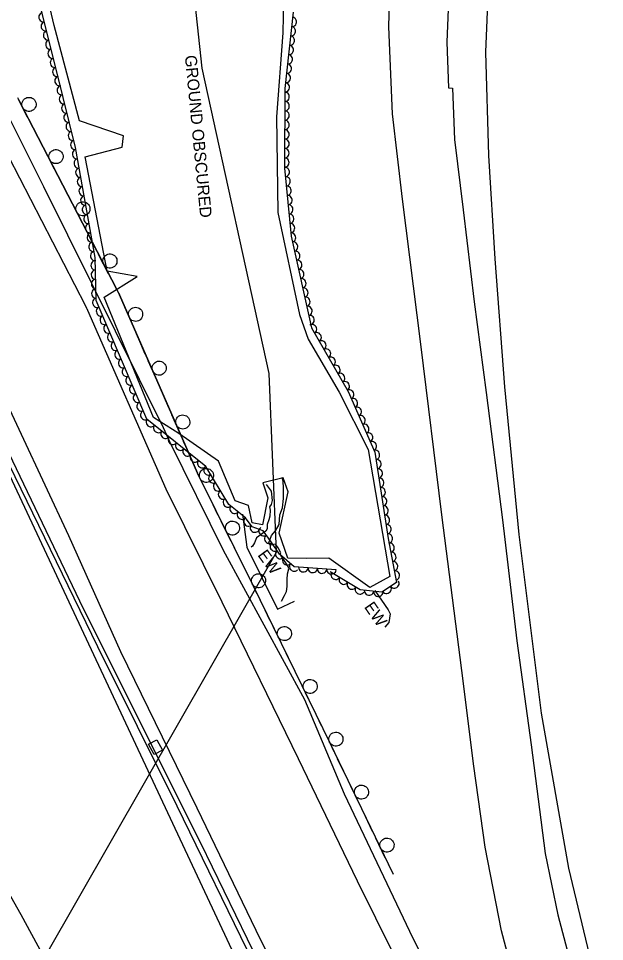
# Model space of a CAD drawing. Extents: x 1746719 to 1766531, y 631721 to 662391.
# Drawn here: x 1761949.9 to 1762199.1, y 638199.1 to 638591.9 of the extents above; entities that cross this region are included whole.
import ezdxf

# ---------------------------------------------------------------- set-up
doc = ezdxf.new("R2010")
doc.units = 0
for name, color, linetype in [('SURVEY - AERIAL SURVEY - Photo Control - Points - Elevations', 7, 'Continuous'), ('SURVEY - AERIAL SURVEY - Photo Control - Points - Locators', 7, 'Continuous'), ('SURVEY - AERIAL SURVEY - Photo Control - Points - Numbers', 7, 'Continuous'), ('SURVEY - AERIAL SURVEY - Photo Control with Text', 7, 'Continuous'), ('SURVEY - CENTERLINE - Existing Roads Text', 7, 'Continuous'), ('SURVEY - CENTERLINE - Preliminary - Development', 7, 'Continuous'), ('SURVEY - CENTERLINE - Preliminary Curve Text', 7, 'Continuous'), ('SURVEY - CONTROL - Points - Locators', 7, 'Continuous')]:
    doc.layers.add(name, color=color, linetype=linetype)

msp = doc.modelspace()

# ---------------------------------------------------------------- linework, layer by layer
at = {"layer": 'SURVEY - AERIAL SURVEY - Photo Control - Points - Elevations'}
for p, q in [((1761949.91, 638557.44), (1761991.7, 638476.49)), ((1761936.58, 638550.56), (1761978.37, 638469.61)), ((1761991.7, 638476.49), (1761992.26, 638475.36)), ((1761992.26, 638475.36), (1761992.44, 638475.01)), ((1761992.44, 638475.01), (1761992.81, 638474.22)), ((1761992.81, 638474.22), (1762026.02, 638398.33)), ((1761978.37, 638469.61), (1761978.85, 638468.64)), ((1761978.85, 638468.64), (1761978.96, 638468.43)), ((1761978.96, 638468.43), (1761979.28, 638467.75)), ((1761979.28, 638467.75), (1762012.58, 638391.68)), ((1761935.82, 638447.38), (1761971.22, 638371.82))]:
    msp.add_line(p, q, dxfattribs=at)
for points in [[(1762189.51, 638754.92), (1762177.71, 638725.71), (1762163.21, 638683.11), (1762156.01, 638652.95), (1762150.08, 638615.49), (1762148.44, 638577.48), (1762149.79, 638533.52), (1762152.38, 638489.61), (1762156.49, 638435.15), (1762162.6, 638372.26), (1762172.14, 638296.33), (1762183.74, 638230.35), (1762199.06, 638166.32)], [(1762133.07, 638606.45), (1762131.97, 638581.73), (1762132.71, 638562.3), (1762134.49, 638562.24), (1762135.23, 638540.36), (1762138.97, 638510.45), (1762143.59, 638471.26), (1762148.75, 638432.72), (1762155.64, 638378.5), (1762161.73, 638327.1), (1762167.84, 638282.76), (1762173.86, 638236.63), (1762179.27, 638210.46), (1762192.08, 638161.63)], [(1762161.96, 638178.55), (1762155.3, 638203.64), (1762148.37, 638239.24), (1762143.48, 638273.66), (1762138.44, 638314.43), (1762129.83, 638380.73), (1762120.98, 638453.32), (1762113.14, 638514.96), (1762108.92, 638551.33), (1762107.4, 638588.32), (1762107.75, 638604.5)], [(1762142.79, 638124.38), (1762142.25, 638125.93), (1762150.96, 638131.28), (1762152.3, 638133.24), (1762153.55, 638134.98), (1762150.91, 638140.96), (1762149.05, 638144.96), (1762147.4, 638144.71), (1762146.19, 638145.03), (1762139.53, 638157.74), (1762117.72, 638200.33), (1762088.54, 638261.83), (1762071.72, 638301.89), (1762037.11, 638365.51), (1762014.19, 638411.73), (1762011.63, 638417.62), (1761960.63, 638520.21), (1761945.31, 638551.2)], [(1761420.3, 638505.12), (1761469.25, 638488.5), (1761533.06, 638468.42), (1761595.06, 638448.42), (1761650.97, 638430.46), (1761705.66, 638412.37), (1761764.6, 638389.95), (1761796.37, 638373.31), (1761821.32, 638357.68), (1761844.39, 638340.34), (1761865.8, 638322.04), (1761884.68, 638304.7), (1761900.43, 638287.9), (1761915.32, 638268.65), (1761930.12, 638247.32), (1761950.94, 638210.57), (1761971.76, 638172.11)], [(1761924.95, 638442.29), (1762056.31, 638161.91), (1762090.32, 638088.89)], [(1762012.58, 638391.68), (1762036.31, 638343.69), (1762068.88, 638276.96), (1762093.91, 638224.95), (1762124.89, 638162.28), (1762146.1, 638118.84)], [(1761971.22, 638371.82), (1761993.23, 638322.52), (1762025.68, 638256.03), (1762050.77, 638203.91), (1762081.81, 638141.12), (1762102.97, 638097.78)]]:
    msp.add_lwpolyline(points, dxfattribs=at)
at = {"layer": 'SURVEY - AERIAL SURVEY - Photo Control - Points - Locators'}
msp.add_lwpolyline([(1762062.99, 638621.31), (1762062.3, 638585.77), (1762059.63, 638550), (1762060.15, 638509.36), (1762069.42, 638465.91), (1762073.07, 638455.39), (1762086.27, 638432.83), (1762098.56, 638408.51), (1762107.82, 638354.38), (1762099.24, 638349.68), (1762081.8, 638362.27), (1762072.39, 638362.09), (1762064.43, 638362.22), (1762060.78, 638372.82), (1762064.59, 638390.45), (1762062.38, 638396.34), (1762053.78, 638394.27), (1762055.86, 638387.85), (1762053.64, 638376.42), (1762049.24, 638377.28), (1762047.65, 638384.6), (1762042.08, 638386.6), (1762034.92, 638403.44), (1762018.1, 638415.27), (1762007.28, 638422.08), (1761986.37, 638473.28), (1762000.43, 638482.07), (1761987.63, 638484.37), (1761978.2, 638532.96), (1761994.05, 638537.11), (1761994.6, 638541.94), (1761975.88, 638548.34), (1761965.03, 638588.81), (1761955.97, 638627.59)], dxfattribs=at)
at = {"layer": 'SURVEY - AERIAL SURVEY - Photo Control - Points - Numbers'}
for p, q in [((1761991.7, 638476.49), (1761949.91, 638557.44)), ((1762026.02, 638398.33), (1761992.81, 638474.22)), ((1761929.92, 638439.81), (1761975.88, 638344.11)), ((1761983.71, 638324.44), (1761938.79, 638416.64)), ((1761975.88, 638344.11), (1761987.01, 638321.54)), ((1762017.38, 638256.74), (1761983.71, 638324.44)), ((1761987.01, 638321.54), (1762027.33, 638241.16)), ((1762062.98, 638162.91), (1762017.38, 638256.74)), ((1762027.33, 638241.16), (1762066.4, 638160.85))]:
    msp.add_line(p, q, dxfattribs=at)
for points in [[(1761953.81, 638549.88), (1761949.91, 638557.44), (1761949.91, 638557.45), (1761949.59, 638558.06)], [(1761957.43, 638542.86), (1761955.28, 638547.04)], [(1761959.59, 638538.69), (1761957.43, 638542.86)], [(1761965.28, 638527.67), (1761961.06, 638535.84)], [(1761968.9, 638520.65), (1761966.74, 638524.83)], [(1761971.06, 638516.47), (1761968.9, 638520.65)], [(1761976.74, 638505.45), (1761972.52, 638513.63)], [(1761980.37, 638498.44), (1761978.21, 638502.61)], [(1761982.52, 638494.26), (1761980.37, 638498.44)], [(1761988.21, 638483.24), (1761983.99, 638491.42)], [(1761991.83, 638476.22), (1761991.7, 638476.49), (1761989.68, 638480.4)], [(1761993.8, 638471.95), (1761992.81, 638474.22), (1761991.83, 638476.22)], [(1761998.78, 638460.59), (1761995.09, 638469.02)], [(1762001.94, 638453.36), (1762000.06, 638457.66)], [(1762003.83, 638449.05), (1762001.94, 638453.36)], [(1762008.8, 638437.69), (1762005.11, 638446.12)], [(1762011.97, 638430.45), (1762010.08, 638434.76)], [(1762013.85, 638426.15), (1762011.97, 638430.45)], [(1762018.82, 638414.79), (1762015.13, 638423.22)], [(1762021.99, 638407.55), (1762020.1, 638411.86)], [(1762023.87, 638403.24), (1762021.99, 638407.55)], [(1762029.14, 638392.02), (1762026.02, 638398.33), (1762026.02, 638398.33), (1762025.15, 638400.31)], [(1762109.28, 638227.61), (1762082.38, 638283.5), (1762049.78, 638350.31), (1762026.02, 638398.33)], [(1762032.64, 638384.94), (1762030.56, 638389.16)], [(1762034.73, 638380.73), (1762032.64, 638384.94)], [(1762040.23, 638369.61), (1762036.15, 638377.86)], [(1762043.73, 638362.53), (1762041.64, 638366.75)], [(1762045.81, 638358.32), (1762043.73, 638362.53)], [(1762051.29, 638347.2), (1762049.78, 638350.31), (1762047.23, 638355.45)], [(1762054.76, 638340.1), (1762052.7, 638344.32)], [(1762056.82, 638335.88), (1762054.76, 638340.1)], [(1762062.26, 638324.73), (1762058.22, 638333)], [(1762065.72, 638317.63), (1762063.66, 638321.85)], [(1762067.78, 638313.41), (1762065.72, 638317.63)], [(1762073.22, 638302.26), (1762069.19, 638310.53)], [(1762076.69, 638295.16), (1762074.62, 638299.39)], [(1762078.75, 638290.94), (1762076.69, 638295.16)], [(1762084.17, 638279.79), (1762082.38, 638283.5), (1762080.15, 638288.06)], [(1762087.59, 638272.67), (1762085.55, 638276.9)], [(1762089.63, 638268.43), (1762087.59, 638272.67)], [(1762095.01, 638257.26), (1762091.02, 638265.55)], [(1762098.43, 638250.14), (1762096.4, 638254.38)], [(1762100.47, 638245.91), (1762098.43, 638250.14)], [(1762105.85, 638234.73), (1762101.86, 638243.02)], [(1762109.28, 638227.61), (1762107.24, 638231.85)]]:
    msp.add_lwpolyline(points, dxfattribs=at)
for centre, start, end in [((1761954.38, 638555.31), 320.571, 320.557), ((1761965.85, 638533.09), 320.571, 320.557), ((1761977.32, 638510.88), 320.571, 320.557), ((1761988.79, 638488.66), 320.571, 320.557), ((1761999.7, 638465.97), 316.9016, 316.8876), ((1762009.72, 638443.07), 316.9016, 316.8876), ((1762019.74, 638420.16), 316.9016, 316.8876), ((1762029.81, 638397.44), 319.5889, 319.5749), ((1762040.89, 638375.03), 319.5889, 319.5749), ((1762051.98, 638352.62), 319.5889, 319.5749), ((1762062.95, 638330.14), 319.2802, 319.2662), ((1762073.92, 638307.67), 319.2802, 319.2662), ((1762084.88, 638285.21), 319.2802, 319.2662), ((1762095.73, 638262.67), 318.9714, 318.9574), ((1762106.58, 638240.14), 318.9714, 318.9574)]:
    msp.add_arc(centre, 3, start, end, dxfattribs=at)
at = {"layer": 'SURVEY - AERIAL SURVEY - Photo Control with Text'}
for points in [[(1762084.98, 638357.21), (1762067.17, 638358.5), (1762060.95, 638363.99), (1762057.35, 638369.19), (1762053.95, 638373.8), (1762049.31, 638375.52), (1762046.38, 638379.44), (1762039.31, 638385.06), (1762029.59, 638401.22), (1762004.42, 638421.41), (1761982.95, 638471.79), (1761982.53, 638490.14), (1761974.2, 638536.92), (1761966.41, 638568.62), (1761951.57, 638627.58)], [(1762066.69, 638594.6), (1762063.19, 638562.1), (1762063.07, 638528.17), (1762065.79, 638499.26), (1762074.49, 638460.19), (1762090.07, 638433.11), (1762101.4, 638407.29), (1762107.06, 638370.54), (1762110.58, 638351.87), (1762104.32, 638347.69), (1762095.15, 638348.74), (1762082.48, 638356.44)]]:
    msp.add_lwpolyline(points, dxfattribs=at)
for centre, major_axis in [((1761960.43, 638592.4), (-0.49, 1.94)), ((1761961.4, 638588.52), (-0.49, 1.94)), ((1762066.24, 638590.38), (-0.21, -1.99)), ((1761962.38, 638584.64), (-0.49, 1.94)), ((1762065.81, 638586.4), (-0.21, -1.99)), ((1761963.36, 638580.76), (-0.49, 1.94)), ((1762065.38, 638582.42), (-0.21, -1.99)), ((1761964.33, 638576.88), (-0.49, 1.94)), ((1762064.95, 638578.44), (-0.21, -1.99)), ((1761965.31, 638573), (-0.49, 1.94)), ((1762064.53, 638574.47), (-0.21, -1.99)), ((1761966.29, 638569.12), (-0.49, 1.94)), ((1762064.1, 638570.49), (-0.21, -1.99)), ((1761967.25, 638565.24), (-0.48, 1.94)), ((1762063.67, 638566.51), (-0.21, -1.99)), ((1761968.2, 638561.35), (-0.48, 1.94)), ((1762063.24, 638562.54), (-0.21, -1.99)), ((1761969.15, 638557.47), (-0.48, 1.94)), ((1762063.18, 638558.54), (-0.01, -2)), ((1761970.11, 638553.59), (-0.48, 1.94)), ((1762063.17, 638554.54), (-0.01, -2)), ((1761971.06, 638549.7), (-0.48, 1.94)), ((1762063.15, 638550.54), (-0.01, -2)), ((1761972.02, 638545.82), (-0.48, 1.94)), ((1762063.14, 638546.54), (-0.01, -2)), ((1761972.97, 638541.93), (-0.48, 1.94)), ((1762063.12, 638542.54), (-0.01, -2)), ((1761973.93, 638538.05), (-0.48, 1.94)), ((1762063.11, 638538.54), (-0.01, -2)), ((1761974.7, 638534.12), (-0.35, 1.97)), ((1762063.09, 638534.54), (-0.01, -2)), ((1761975.4, 638530.19), (-0.35, 1.97)), ((1762063.07, 638530.54), (-0.01, -2)), ((1761976.1, 638526.25), (-0.35, 1.97)), ((1762063.22, 638526.55), (0.19, -1.99)), ((1761976.8, 638522.31), (-0.35, 1.97)), ((1762063.59, 638522.56), (0.19, -1.99)), ((1761977.5, 638518.37), (-0.35, 1.97)), ((1762063.97, 638518.58), (0.19, -1.99)), ((1761978.2, 638514.43), (-0.35, 1.97)), ((1762064.35, 638514.6), (0.19, -1.99)), ((1761978.9, 638510.5), (-0.35, 1.97)), ((1762064.72, 638510.62), (0.19, -1.99)), ((1761979.6, 638506.56), (-0.35, 1.97)), ((1762065.1, 638506.63), (0.19, -1.99)), ((1761980.3, 638502.62), (-0.35, 1.97)), ((1762065.47, 638502.65), (0.19, -1.99)), ((1761981.01, 638498.68), (-0.35, 1.97)), ((1762065.92, 638498.68), (0.43, -1.95)), ((1761981.71, 638494.74), (-0.35, 1.97)), ((1762066.79, 638494.78), (0.43, -1.95)), ((1761982.41, 638490.8), (-0.35, 1.97)), ((1762067.66, 638490.87), (0.43, -1.95)), ((1761982.6, 638486.82), (-0.05, 2)), ((1762068.53, 638486.97), (0.43, -1.95)), ((1761982.69, 638482.82), (-0.05, 2)), ((1762069.4, 638483.06), (0.43, -1.95)), ((1761982.78, 638478.82), (-0.05, 2)), ((1762070.27, 638479.16), (0.43, -1.95)), ((1761982.88, 638474.82), (-0.05, 2)), ((1762071.14, 638475.25), (0.43, -1.95)), ((1761983.32, 638470.9), (-0.78, 1.84)), ((1762072.01, 638471.35), (0.43, -1.95)), ((1761984.89, 638467.22), (-0.78, 1.84)), ((1762072.88, 638467.45), (0.43, -1.95)), ((1761986.46, 638463.54), (-0.78, 1.84)), ((1762073.75, 638463.54), (0.43, -1.95)), ((1761988.03, 638459.86), (-0.78, 1.84)), ((1762074.78, 638459.7), (1, -1.73)), ((1761989.6, 638456.18), (-0.78, 1.84)), ((1762076.77, 638456.23), (1, -1.73)), ((1761991.17, 638452.5), (-0.78, 1.84)), ((1762078.77, 638452.77), (1, -1.73)), ((1761992.73, 638448.82), (-0.78, 1.84)), ((1762080.76, 638449.3), (1, -1.73)), ((1761994.3, 638445.14), (-0.78, 1.84)), ((1762082.75, 638445.83), (1, -1.73)), ((1761995.87, 638441.46), (-0.78, 1.84)), ((1762084.75, 638442.36), (1, -1.73)), ((1762086.74, 638438.9), (1, -1.73)), ((1761997.44, 638437.78), (-0.78, 1.84)), ((1762088.74, 638435.43), (1, -1.73)), ((1761999.01, 638434.1), (-0.78, 1.84)), ((1762090.6, 638431.9), (0.8, -1.83)), ((1762000.58, 638430.42), (-0.78, 1.84)), ((1762092.21, 638428.23), (0.8, -1.83)), ((1762002.14, 638426.74), (-0.78, 1.84)), ((1762093.82, 638424.57), (0.8, -1.83)), ((1762003.71, 638423.06), (-0.78, 1.84)), ((1762095.43, 638420.91), (0.8, -1.83)), ((1762006.14, 638420.03), (-1.56, 1.25)), ((1762009.26, 638417.53), (-1.56, 1.25)), ((1762097.03, 638417.25), (0.8, -1.83)), ((1762012.38, 638415.03), (-1.56, 1.25)), ((1762015.5, 638412.52), (-1.56, 1.25)), ((1762098.64, 638413.58), (0.8, -1.83)), ((1762018.62, 638410.02), (-1.56, 1.25)), ((1762100.25, 638409.92), (0.8, -1.83)), ((1762021.74, 638407.52), (-1.56, 1.25)), ((1762024.86, 638405.02), (-1.56, 1.25)), ((1762101.58, 638406.18), (0.3, -1.98)), ((1762027.98, 638402.52), (-1.56, 1.25)), ((1762102.18, 638402.22), (0.3, -1.98)), ((1762030.59, 638399.56), (-1.03, 1.71)), ((1762032.65, 638396.14), (-1.03, 1.71)), ((1762102.79, 638398.27), (0.3, -1.98)), ((1762034.71, 638392.71), (-1.03, 1.71)), ((1762103.4, 638394.32), (0.3, -1.98)), ((1762036.77, 638389.28), (-1.03, 1.71)), ((1762104.01, 638390.36), (0.3, -1.98)), ((1762038.83, 638385.85), (-1.03, 1.71)), ((1762104.62, 638386.41), (0.3, -1.98)), ((1762041.71, 638383.14), (-1.57, 1.24)), ((1762105.23, 638382.45), (0.3, -1.98)), ((1762044.84, 638380.65), (-1.57, 1.24)), ((1762047.6, 638377.8), (-1.2, 1.6)), ((1762105.83, 638378.5), (0.3, -1.98)), ((1762050.39, 638375.12), (-1.88, 0.7)), ((1762054.07, 638373.64), (-1.19, 1.61)), ((1762106.44, 638374.55), (0.3, -1.98)), ((1762056.44, 638370.42), (-1.19, 1.61)), ((1762107.05, 638370.59), (0.3, -1.98)), ((1762058.76, 638367.16), (-1.14, 1.64)), ((1762107.79, 638366.66), (0.37, -1.97)), ((1762061.06, 638363.89), (-1.5, 1.32)), ((1762064.06, 638361.24), (-1.5, 1.32)), ((1762108.53, 638362.73), (0.37, -1.97)), ((1762067.06, 638358.6), (-1.5, 1.32)), ((1762109.27, 638358.8), (0.37, -1.97)), ((1762071.01, 638358.22), (-1.99, 0.14)), ((1762075, 638357.93), (-1.99, 0.14)), ((1762078.99, 638357.64), (-1.99, 0.14)), ((1762082.98, 638357.35), (-1.99, 0.14)), ((1762084.73, 638355.07), (-1.71, 1.04)), ((1762110.01, 638354.87), (0.37, -1.97)), ((1762088.15, 638353), (-1.71, 1.04)), ((1762091.57, 638350.92), (-1.71, 1.04)), ((1762109.79, 638351.35), (-1.66, -1.11)), ((1762094.99, 638348.84), (-1.71, 1.04)), ((1762098.94, 638348.31), (-1.99, 0.23)), ((1762102.91, 638347.85), (-1.99, 0.23)), ((1762106.47, 638349.12), (-1.66, -1.11))]:
    msp.add_ellipse(centre, major_axis=major_axis, ratio=0.940188, start_param=0, end_param=3.141593, dxfattribs=at)
at = {"layer": 'SURVEY - CENTERLINE - Existing Roads Text'}
for points in [[(1762045.15, 638381.01), (1762047.01, 638366.95), (1762060.07, 638340.59), (1762067.28, 638343.86)], [(1762101.4, 638348.53), (1762107.14, 638340.26), (1762107.95, 638338.53), (1762107.4, 638334.78), (1762105.6, 638332.88)]]:
    msp.add_lwpolyline(points, dxfattribs=at)
at = {"layer": 'SURVEY - CENTERLINE - Preliminary Curve Text'}
msp.add_line((1762008.17, 638281.82), (1762008.17, 638281.82), dxfattribs=at)
msp.add_lwpolyline([(1762005.24, 638283.11), (1762008.79, 638284.96), (1762011.1, 638280.53), (1762007.55, 638278.68), (1762005.24, 638283.11)], dxfattribs=at)
at = {"layer": 'SURVEY - CONTROL - Points - Locators'}
for points in [[(1761891.07, 637793.83), (1761899.22, 637993.48), (1761897.33, 638030.68), (1761892.33, 638078.24), (1761896.45, 638096.58), (1761907.7, 638114.75), (1761933.23, 638143.98), (1762059.54, 638364.83), (1762056.48, 638440.73), (1762027.97, 638570.7), (1762020.66, 638639.38), (1762017.5, 638702.57), (1762076.59, 639071.99), (1762064.24, 639158.94), (1762062.45, 639225.72), (1762077.73, 639301.51), (1762104.06, 639375.67)], [(1762061.68, 638343.94), (1762063.03, 638346.36), (1762063.91, 638348), (1762064.21, 638350.23), (1762064.13, 638353.14), (1762064.3, 638355.5), (1762064.82, 638357.71), (1762064.62, 638358.71), (1762063.61, 638360.18), (1762062.57, 638361.68), (1762061.13, 638363.91), (1762061.47, 638364.54), (1762060.29, 638366.68), (1762059.24, 638368.19), (1762057.04, 638367.7), (1762056.35, 638368.73), (1762057.45, 638371.85), (1762059.25, 638373.89), (1762060.76, 638376.56), (1762061.09, 638380.66), (1762062.16, 638383.68), (1762062.51, 638387.54), (1762062.59, 638391.97), (1762062.4, 638394.95), (1762062.01, 638396.56)], [(1762055.28, 638393.63), (1762057.28, 638390.74), (1762057.76, 638386.7), (1762057.38, 638385.08), (1762056.59, 638384.04), (1762056.85, 638382.6), (1762056.72, 638380.03), (1762056.3, 638378.59), (1762055.62, 638376.55), (1762055.6, 638374.7), (1762055.06, 638373.69), (1762053.63, 638372.7), (1762052.12, 638371.65), (1762051.08, 638370.94), (1762050.21, 638368.76), (1762049.38, 638367.4), (1762048.88, 638366.93)]]:
    msp.add_lwpolyline(points, dxfattribs=at)

# ---------------------------------------------------------------- texts
at = {"layer": 'SURVEY - AERIAL SURVEY - Photo Control - Points - Locators'}
msp.add_text('GROUND OBSCURED', height=5, rotation=275.4356, dxfattribs=at).set_placement((1762020.63, 638576.02))
at = {"layer": 'SURVEY - CENTERLINE - Preliminary - Development'}
for rotation, p in [(306.307, (1762051.36, 638363.5)), (304.741, (1762096.69, 638341.46))]:
    msp.add_text('EW', height=5, rotation=rotation, dxfattribs=at).set_placement(p)

doc.saveas('drawing.dxf')
